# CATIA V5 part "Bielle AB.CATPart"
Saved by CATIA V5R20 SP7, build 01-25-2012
Part number: Bielle AB
Publications: "Point.1", "Point.2", "Droite.2", "Droite.3"
Bounding box of the stored display mesh (mm): x -10 to 10, y 0 to 240, z 0 to 0
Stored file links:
  U:\IAO\IAO\IAO\Bielle AB.CATPart
  U:\IAO\IAO\IAO\Squelette.CATProduct
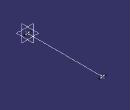
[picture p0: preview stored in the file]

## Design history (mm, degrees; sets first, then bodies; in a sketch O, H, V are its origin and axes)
External parameters (linked from other documents)
  `External.Longueur AB` = 240 mm
  `External.Longueur Demi Pivot` = 10 mm
Body1 (main body)
  Point1: (0, 0, 0)
  Line1: type PtDir, RefPoint Point1, Direction zx-plane, Start 0, End 240 {= `External.Longueur AB`}
  Point2: (0, 0, 0), relative to vertex of Line1
  Line2: type PtDir, RefPoint Point1, Direction yz-plane, Start -10, End 10 {= `External.Longueur Demi Pivot`}
  Line3: type PtDir, RefPoint Point2, Direction yz-plane, Start -10, End 10 {= `External.Longueur Demi Pivot`}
